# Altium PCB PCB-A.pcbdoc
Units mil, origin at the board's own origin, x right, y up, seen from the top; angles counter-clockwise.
Board outline 5415 x 2695 mil, 4 copper layers (Top Layer, Inner1, Inner2, Bottom Layer); 67 components, 115 nets, 401 pads, 220 vias.
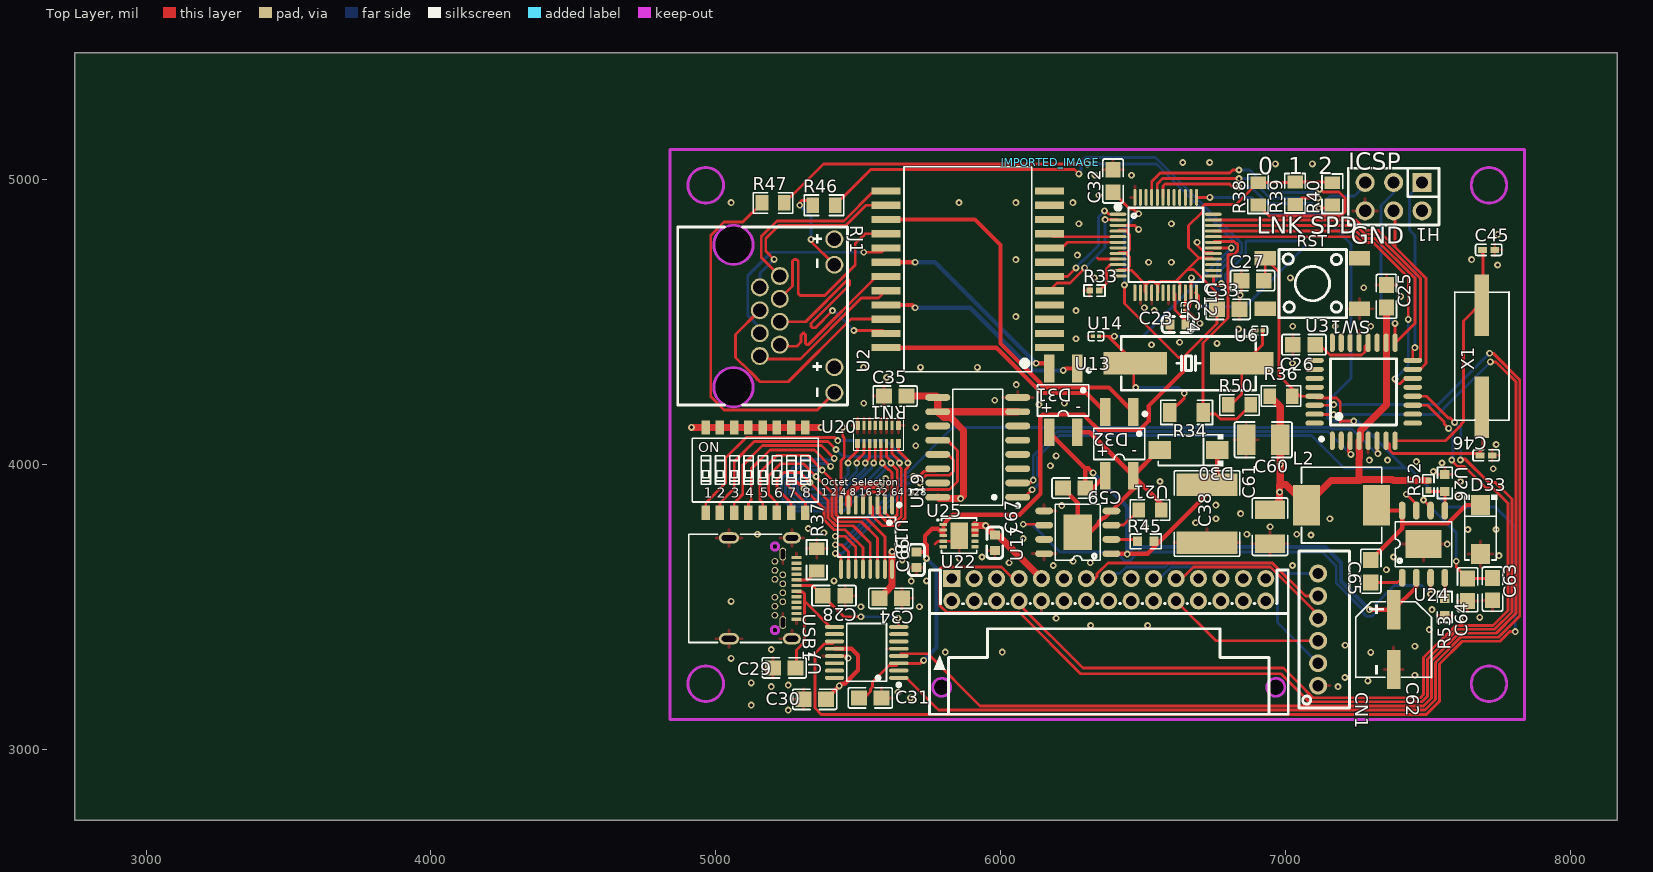
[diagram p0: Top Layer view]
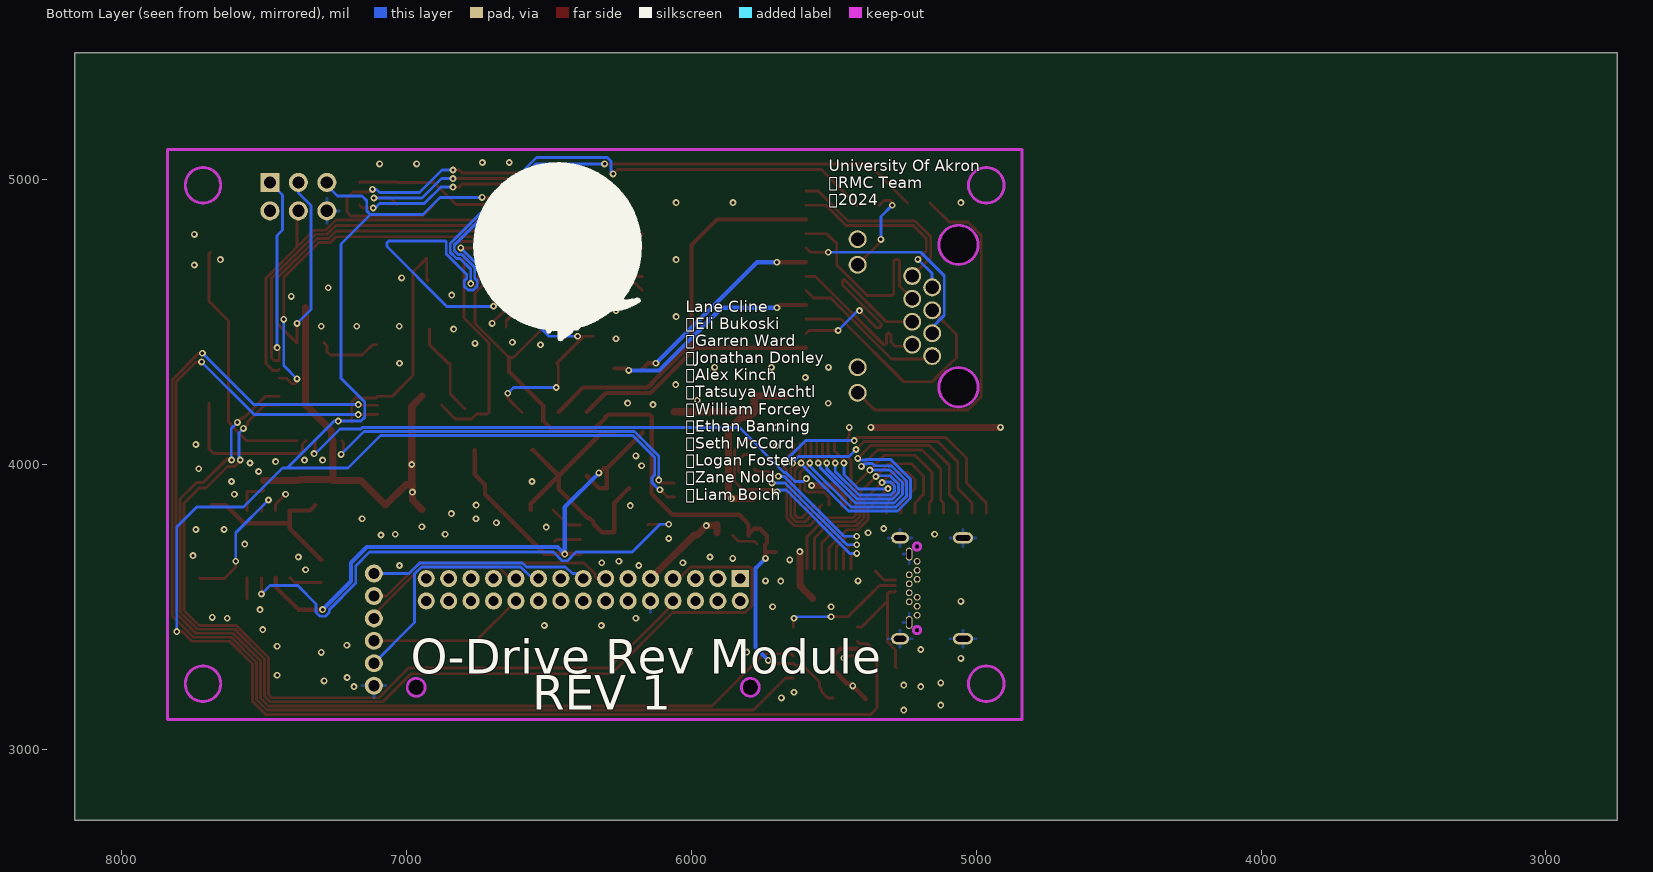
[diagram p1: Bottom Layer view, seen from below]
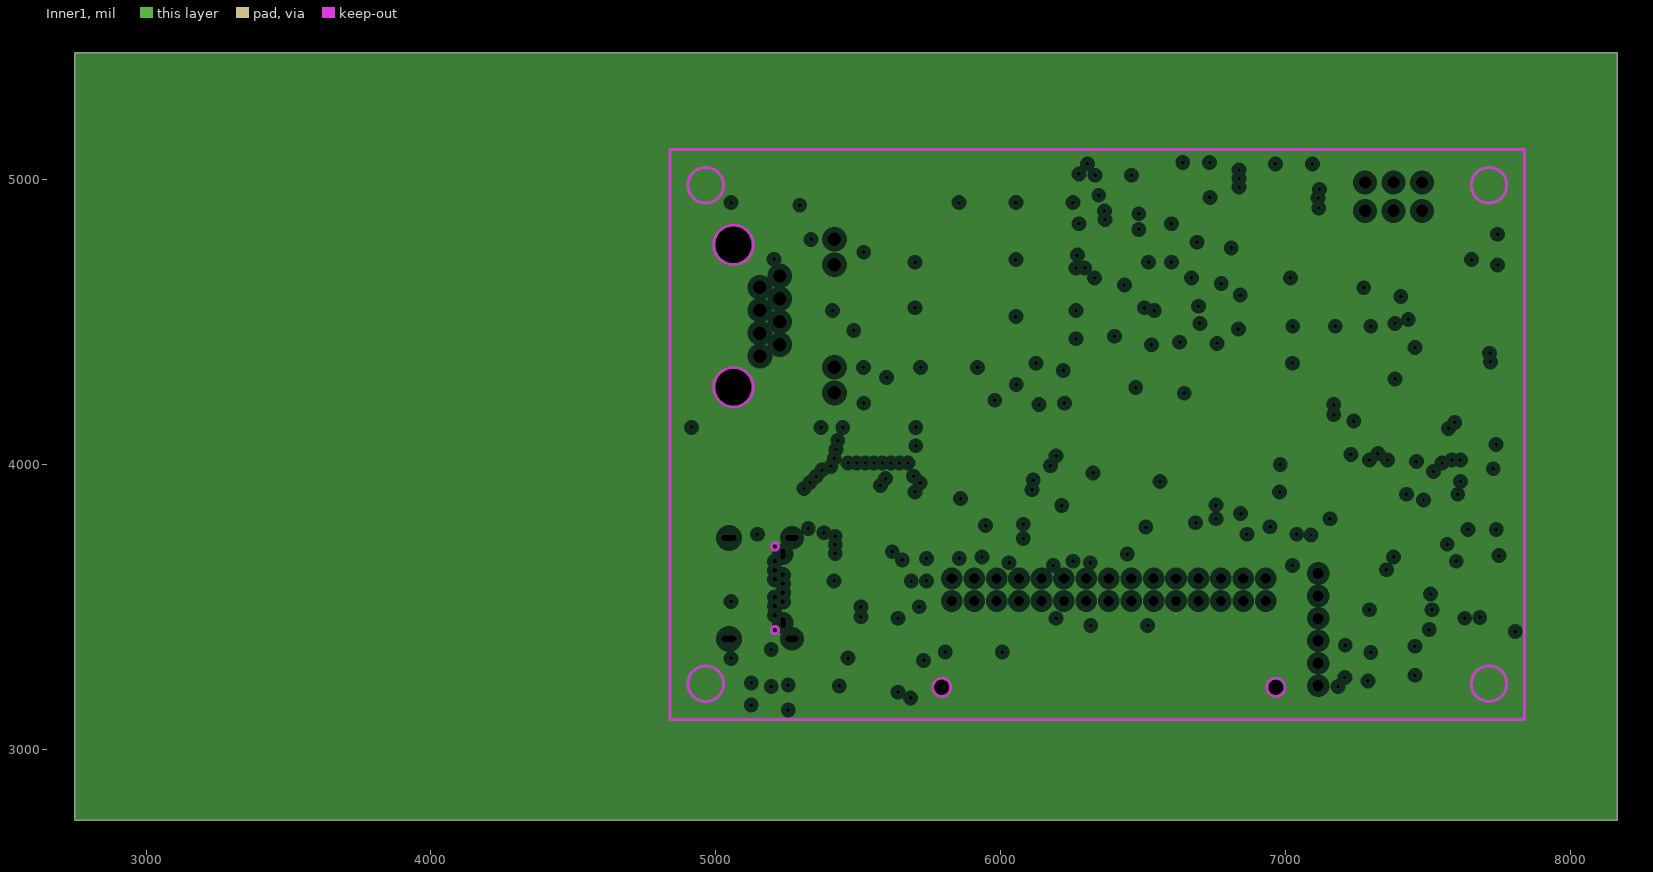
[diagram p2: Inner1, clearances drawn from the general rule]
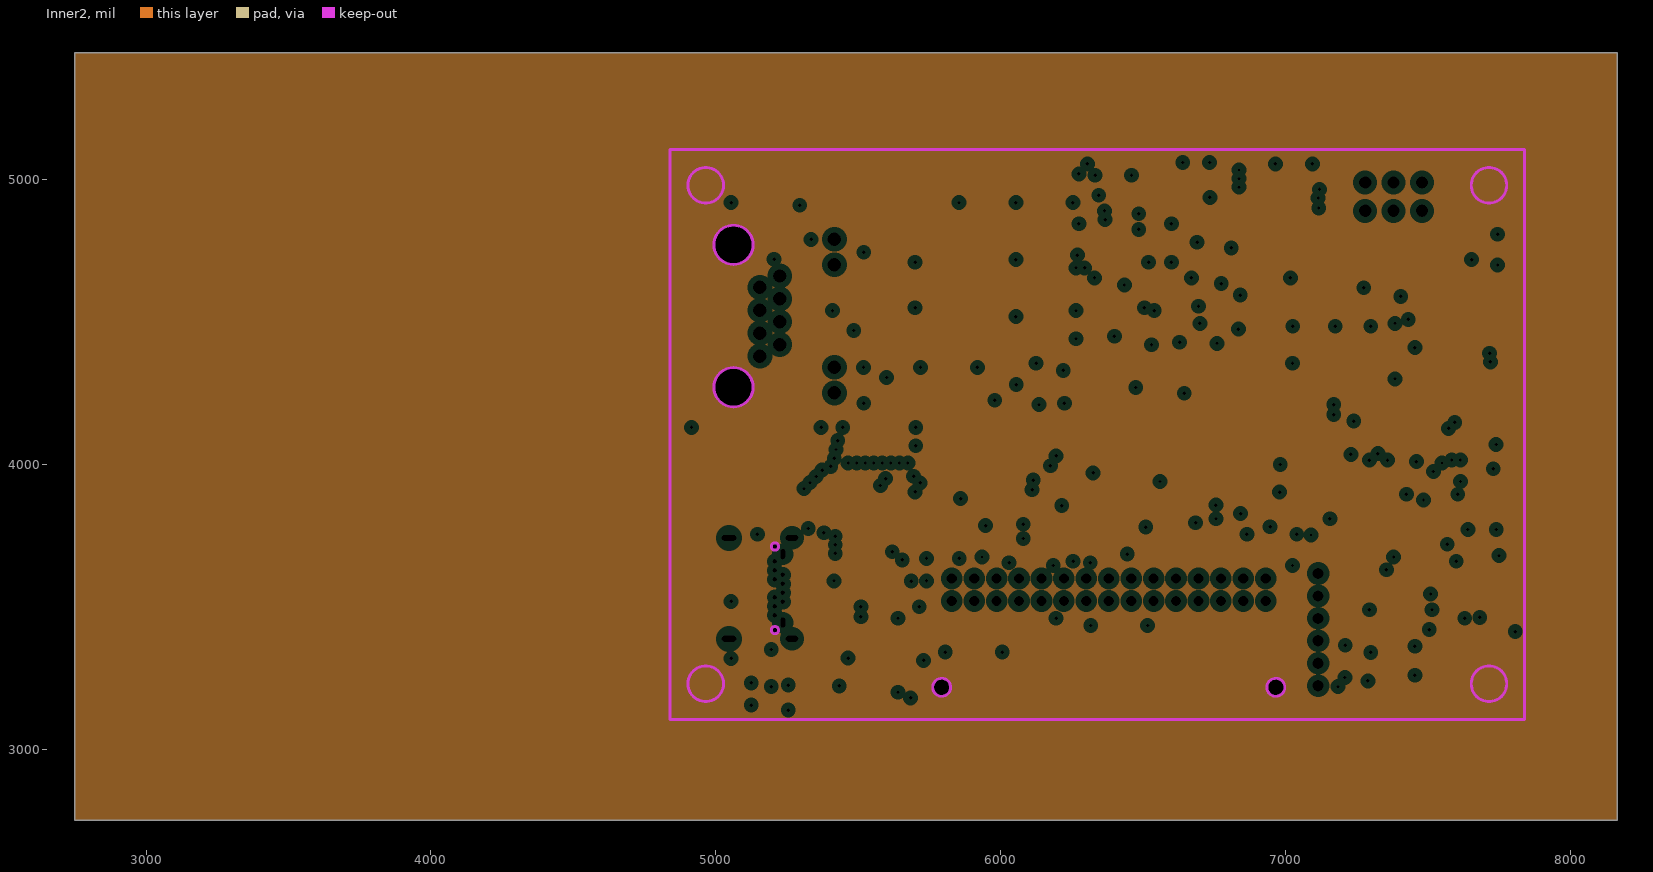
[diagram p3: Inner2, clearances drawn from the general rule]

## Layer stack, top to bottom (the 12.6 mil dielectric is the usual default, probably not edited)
Top Layer: signal copper (thickness not stored)
Dielectric: dielectric 12.6, FR-4, Dk 4.8
Inner1: plane copper (thickness not stored)
Dielectric: dielectric 12.6, FR-4, Dk 4.8
Inner2: plane copper (thickness not stored)
Dielectric: dielectric 12.6, FR-4, Dk 4.8
Bottom Layer: signal copper (thickness not stored)

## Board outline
8165,2750 2750,2750 2750,5445 8165,5445

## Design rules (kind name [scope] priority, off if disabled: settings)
Clearance copperThickness1oz [All] p1: gap=7 ignorepadtopadclearanceinfootprint=FALSE except(4: Track-Track; 6: Track-SMDPad SMDPad-SMDPad Track-THPad SMDPad-THPad THPad-THPad Track-Via SMDPad-Via THPad-Via Via-Via SMDPad-Fill THPad-Fill Via-Fill Fill-Fill Track-Region SMDPad-Region THPad-Region Via-Region Region-Region Track-Poly SMDPad-Poly THPad-Poly Via-Poly Fill-Poly Region-Poly Poly-Poly Track-Text SMDPad-Text THPad-Text Via-Text Fill-Text Region-Text Poly-Text Text-Text; 6.9: Track-Hole SMDPad-Hole THPad-Hole Via-Hole Fill-Hole Region-Hole Poly-Hole Text-Hole Sheet-Hole; 11.8: Track-Fill Fill-Region Track-Sheet SMDPad-Sheet THPad-Sheet Via-Sheet Fill-Sheet Region-Sheet Poly-Sheet Text-Sheet)
Clearance copperThickness2oz [All] p1: gap=7 ignorepadtopadclearanceinfootprint=FALSE except(6: Track-SMDPad SMDPad-SMDPad Track-THPad SMDPad-THPad THPad-THPad Track-Via SMDPad-Via THPad-Via Via-Via SMDPad-Fill THPad-Fill Via-Fill Fill-Fill Track-Region SMDPad-Region THPad-Region Via-Region Region-Region Track-Poly SMDPad-Poly THPad-Poly Via-Poly Fill-Poly Region-Poly Poly-Poly Track-Text SMDPad-Text THPad-Text Via-Text Fill-Text Region-Text Poly-Text Text-Text; 6.9: Track-Hole SMDPad-Hole THPad-Hole Via-Hole Fill-Hole Region-Hole Poly-Hole Text-Hole Sheet-Hole; 8: Track-Track; 11.8: Track-Fill Fill-Region Track-Sheet SMDPad-Sheet THPad-Sheet Via-Sheet Fill-Sheet Region-Sheet Poly-Sheet Text-Sheet)
DiffPairsRouting differentialPair [All] p1: maxuncoupledlength=10 maxlimit=6 mostfreqgap=6 toplayer_minwidth=5 toplayer_prefwidth=10 toplayer_maxwidth=100 bottomlayer_minwidth=5 bottomlayer_prefwidth=10 bottomlayer_maxwidth=100
DiffPairsRouting differentialPair1 [All] p1: maxuncoupledlength=10 maxlimit=6 mostfreqgap=6 toplayer_minwidth=5 toplayer_prefwidth=10 toplayer_maxwidth=100 bottomlayer_minwidth=5 bottomlayer_prefwidth=10 bottomlayer_maxwidth=100
PasteMaskExpansion pasteMaskExpansion [All] p1:
PlaneConnect innerPlane [All] p1: planeconnectstyle=Relief reliefexpansion=20 reliefentries=4 reliefconductorwidth=10 reliefairgap=10
PolygonConnect copperRegion [All] p1: connectstyle=Relief reliefentries=4 reliefconductorwidth=10 polygonreliefangle="90 Angle" airgapwidth=10
RoutingVias viaSize [All] p1: viastyle="Through Hole" holewidth=12 minholewidth=11.8 maxholewidth=248 width=24 minwidth=19.7 maxwidth=393.7
SolderMaskExpansion solderMaskExpansion [All] p1: useseparateexpansions=TRUE expansion=2 expansionbottom=2
Width copperThickness1oz [All] p1: maxlimit=100 minlimit=5 preferedwidth=10
Width copperThickness2oz [All] p1: maxlimit=100 minlimit=8 preferedwidth=10
Width powa [All] p1: maxlimit=50 minlimit=10 preferedwidth=25
Width 3v [All] p1: maxlimit=100 minlimit=10 preferedwidth=15

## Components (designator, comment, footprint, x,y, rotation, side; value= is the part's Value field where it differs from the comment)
C23 "CL10A475KQ8NNNC" C0603 6622.81,4490.85 r0 top
C24 "CL02A103KQ2NNNC" C01005 6645,4550 r270 top
C25 "0805B104K500NT" C0805 7355,4590 r90 top
C26 "0805B104K500NT" C0805 7065.69,4420.24 r0 top
C27 "0805B104K500NT" C0805 6885,4645 r0 top
C28 "CL21C470JBANNNC" C0805 5415.4,3539.06 r180 top
C29 "CL21C470JBANNNC" C0805 5240.7,3285.81 r0 top
C30 "0805B104K500NT" C0805 5347.65,3175.41 r0 top
C31 "0805B104K500NT" C0805 5543,3180.41 r0 top
C32 "0805B104K500NT" C0805 6395,4995 r90 top
C33 "0805B104K500NT" C0805 6799.25,4544.63 r0 top
C34 "0805B104K500NT" C0805 5615,3530 r180 top
C35 "0805B104K500NT" C0805 5630,4240 r0 top
C38 "FS55X106K101EHG" C2220 6724.99,3827.21 r90 top
C45 "CC0402JRNPO9BN120" C0402 7713.97,4753.41 r0 top
C46 "CC0402JRNPO9BN120" C0402 7705,4031.99 r180 top
C59 "0805B104K500NT" C0805 6258.25,3916.73 r180 top
C60 "CS3225X7R476K160NRL" C1210 6922.35,4086.37 r0 top
C61 "CS3225X7R476K160NRL" C1210 6946.27,3781.37 r90 top
C62 "EEEFK1J100P" CAP-SMD_BD6.3-L6.6-W6.6-FD 7380,3385 r270 top
C63 "0805F403M500NT" C0805 7727.35,3562.13 r90 top
C64 "0805F403M500NT" C0805 7640,3560 r90 top
C65 "0805B104K500NT" C0805 7300,3625 r270 top
C66 "CL10A225KO8NNNC" C0603 5705,3665 r90 top
C67 "CL10A225KO8NNNC" C0603 5980,3725 r90 top
CN1 "B6B-PH-K-S(LF)(SN)_C131342" CONN-TH_B6B-PH-K-S 7115,3420 r270 top
D30 "SMAJ58A" SMA_L4.4-W2.8-LS5.4-RD 6660,4050 r180 top
D31 "MB110S_C382811" MBS_L4.7-W4.0-P2.50-LS7.0-BL 6220,4225 r180 top
D32 "MB110S_C382811" MBS_L4.7-W4.0-P2.50-LS7.0-BL 6416.86,4072.27 r180 top
D33 "SS36_C727061" SMA_L4.4-W2.6-LS5.0-RD 7685,3771.37 r270 top
H1 "10897060" HDR-TH_6P-P2.54-V-M-R2-C3-S2.54 7380,4940 r180 top
IMPORTED_IMAGE "IMPORTED_IMAGE" IMPORTED_IMAGE 6175,5060 r0 top
L2 "FXL0630-8R2-M" IND-SMD_L7.0-W6.6_FXL0630 7197.3,3857.13 r0 top
R33 "0402WGF1242TCE" R0402 6330,4610 r0 top
R34 "1206W4F1004T5E" R1206 6653.04,4182.26 r0 top
R36 "0805W8F1002T5E" R0805 6985,4240 r0 top
R37 "ARG05BTC5001N" R0805 5355,3665 r90 top
R38 "0805W8F0000T5E_C17477" R0805 6904.25,4949.88 r90 top
R39 "0805W8F0000T5E_C17477" R0805 7034.25,4951.98 r90 top
R40 "0805W8F0000T5E_C17477" R0805 7165,4950 r90 top
R45 "0603WAF2492T5E" R0603 6510,3730 r0 top
R46 "ARG05DTC2500N" R0805 5380,4910 r0 top
R47 "ARG05DTC2500N" R0805 5201.69,4918 r0 top
R50 "RC0805JR-070RL" R0805 6838.76,4208.94 r0 top
R52 "RC0402FR-07100KL" R0402 7502.16,3926.37 r90 top
R53 "0603WAF4992T5E" R0603 7559.36,3499.4 r90 top
RJ1 "HC-RJ45-5JA-1-5" RJ45-TH_HC-RJ45-5JA-1-5 5285.86,4520.98 r270 top
RN1 "YC248-JR-0710KL" RES-ARRAY-SMD_1606-16P-L4.0-W1.6-BL 5570,4105 r180 top
SW1 "PTS645SK50SMTR92LFS" KEY-SMD_4P-L6.0-W6.0-P4.50-LS9.0 7095,4635 r180 top
U2 "G24102CE-Z" SMD-24_L18.2-W12.2-P1.27_G24102CE-Z 5885,4685 r90 top
U3 "ATMEGA328PB-AU" TQFP-32_L7.0-W7.0-P0.80-LS9.0-BL 7275,4255 r0 top
U6 "GJM0335C1E180GB01D" C0201 6910,4470 r0 top
U7 "FT230XS-R" SSOP-16_L5.0-W4.4-P0.65-LS6.4-BL 5530,3340 r90 top
U12 "W5500" LQFP-48_L7.0-W7.0-P0.50-LS9.0-BL 6580,4770 r270 top
U13 "ECS-250-18-5PX-CKM-TR" HC-49-SMD_L12.0-W4.8 6660,4355 r0 top
U14 "GJM0335C1E180GB01D" C0201 6335,4450 r0 top
U17 "TPS2378DDAR" SO-8_L4.9-W3.9-P1.27-LS6.0-BL-EP 6271.2,3761.73 r90 top
U18 "SN74HC151PWR" TSSOP-16_L5.0-W4.4-P0.65-LS6.4-BL 5530,3745 r180 top
U19 "SN74LS161ANSR" SOIC-16_L10.8-W5.5-P1.27-LS7.8-BL 5920,4060 r90 top
U20 "DV7SA-08F-01" SW-SMD_DV7SA-08F-01 5140,3980 r0 top
U21 "CR0805F863R4G" R0805 6525,3840 r180 top
U22 "S30B-PUDSS-1(LF)(SN)" CONN-TH_S30B-PUDSS-1 6380,3560 r0 top
U24 "LMR16030SDDAR" SO-8_L4.9-W3.9-P1.27-LS6.0-BL-EP 7485,3720 r0 top
U25 "NCP3335AMN330R2G" DFN-10_L3.0-W3.0-P0.50-BL-EP-1 5855,3750 r270 top
U26 "FRC0603F1782TS" R0603 7560,3935 r270 top
USB1 "HC-TYPE-C-24P-DS10.0-CH2.75S-5A-04" USB-TYPE-C-SMD_HC-TYPE-C-24P-DS10.0-CH2.75S-5A-04 5165,3565 r270 top
X1 "X49SM16MSD2SC" HC-49S_L11.4-W4.8 7690,4380 r90 top

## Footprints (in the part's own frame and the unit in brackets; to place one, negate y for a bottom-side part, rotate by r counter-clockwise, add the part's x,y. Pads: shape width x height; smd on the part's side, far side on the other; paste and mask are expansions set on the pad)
C0201 [mil]
  rect 14.51x12.76 smd: 1(-10.8,0) 2(10.8,0)
  silkscreen extent -27,-15 27,15
C0402 [mm]
  rect 0.79x0.54 smd: 1(-0.545,0) 2(0.545,0)
  silkscreen extent -1.17,-0.5 1.17,0.5
C0603 [mm]
  rect 0.8x0.9 smd: 1(-0.7,0) 2(0.7,0)
  silkscreen extent -1.41,-0.71 1.39,0.72
C0805 [mm]
  rect 1.41x1.35 smd: 1(-1,0) 2(1,0)
  silkscreen extent -1.96,-0.9 1.96,0.9
C01005 [mm]
  rect 0.21x0.22 smd: 1(-0.195,0) 2(0.195,0)
  silkscreen extent -0.46,-0.27 0.46,0.27
C1210 [mm]
  rect 1.635x2.7 smd: 1(-1.517,0) 2(1.517,0)
  silkscreen extent -2.56,-1.58 2.56,1.58
C2220 [mm]
  rect 2.01x5.4 smd: 1(-2.58,0) 2(2.58,0)
  silkscreen extent -3.81,-2.93 3.81,2.93
CAP-SMD_BD6.3-L6.6-W6.6-FD [mm]
  rect 3.5x1.2 smd: 1(-2.67,0) 2(2.67,0)
  silkscreen extent -3.38,-3.38 3.38,3.38
CONN-TH_B6B-PH-K-S [mm]
  round 1.6 hole 1: 1(5,0) 2(3,0) 3(1,0) 4(-1,0) 5(-3,0) 6(-5,0)
  silkscreen extent -7,-1.7 7,2.8
CONN-TH_S30B-PUDSS-1 [mil]
  rect 60x60 hole 36: 1(-551.18,39.37)
  round 60 hole 36: 2(-551.18,-39.37) 3(-472.44,39.37) 4(-472.44,-39.37) 5(-393.7,39.37) 6(-393.7,-39.37) 7(-314.96,39.37) 8(-314.96,-39.37) 9(-236.22,39.37) 10(-236.22,-39.37) 11(-157.48,39.37) 12(-157.48,-39.37) 13(-78.74,39.37) 14(-78.74,-39.37) 15(0,39.37) 16(0,-39.37) 17(78.74,39.37) 18(78.74,-39.37) 19(157.48,39.37) 20(157.48,-39.37) 21(236.22,39.37) 22(236.22,-39.37) 23(314.96,39.37) 24(314.96,-39.37) 25(393.7,39.37) 26(393.7,-39.37) 27(472.44,39.37) 28(472.44,-39.37) 29(551.18,39.37) 30(551.18,-39.37)
  Multi-Layer board cut-out: -555.12,-342.52 -558.24,-328.85 -566.98,-317.89 -579.61,-311.81 -593.62,-311.81 -606.25,-317.89 -614.99,-328.85 -618.11,-342.52 -618.11,-342.52 -614.99,-356.19 -606.25,-367.14 -593.62,-373.23 -579.6,-373.23 -566.98,-367.14 -558.24,-356.18 -555.12,-342.52
  Multi-Layer board cut-out: 618.11,-342.52 613.79,-326.9 602.27,-315.5 586.61,-311.33 570.95,-315.5 559.44,-326.9 555.12,-342.52 555.12,-342.52 559.44,-358.14 570.96,-369.54 586.61,-373.71 602.27,-369.54 613.79,-358.14 618.11,-342.52
  Multi-Layer keep-out circle w10: c-586.61,-342.52 r31.5
  Multi-Layer keep-out circle w10: c586.61,-342.52 r31.5
  silkscreen extent -630,-437 630,69
DFN-10_L3.0-W3.0-P0.50-BL-EP-1 [mm]
  rect 0.29x0.65 smd: 1(-1,-1.411) 2(-0.5,-1.411) 3(0,-1.411) 4(0.5,-1.411) 5(1,-1.411) 6(1,1.411) 7(0.5,1.411) 8(0,1.411) 9(-0.5,1.411) 10(-1,1.411)
  rect 2.35x1.58 smd: 11(0,0)
  silkscreen extent -1.58,-1.98 1.58,1.58
HC-49-SMD_L12.0-W4.8 [mm]
  rect 5.7x2 smd: 1(-4.75,0) 2(4.75,0)
  silkscreen extent -6,-2.4 6,2.4
HC-49S_L11.4-W4.8 [mm]
  rect 5.5x1.3 smd: 1(-4.553,0) 2(4.553,0)
  silkscreen extent -5.71,-2.41 5.71,2.41
HDR-TH_6P-P2.54-V-M-R2-C3-S2.54 [mm]
  rect 1.7x1.7 hole 1.1: 1(-2.54,-1.27)
  round 1.7 hole 1.1: 2(-2.54,1.27) 3(0,-1.27) 4(0,1.27) 5(2.54,-1.27) 6(2.54,1.27)
  silkscreen extent -4.04,-2.54 4.04,2.54
IMPORTED_IMAGE [mil]
IND-SMD_L7.0-W6.6_FXL0630 [mm]
  rect 2.424x3.62 smd: 1(3.128,0) 2(-3.128,0)
  silkscreen extent -3.58,-3.38 3.58,3.38
KEY-SMD_4P-L6.0-W6.0-P4.50-LS9.0 [mm]
  rect 1.9x1.3 smd: 1(-4.2,2.25) 2(4.2,2.25) 3(-4.2,-2.25) 4(4.2,-2.25)
  silkscreen extent -3.05,-3.05 2.98,3.05
LQFP-48_L7.0-W7.0-P0.50-LS9.0-BL [mm]
  oval 0.27x1.5 smd: 1(-2.75,-4.25) 2(-2.25,-4.25) 3(-1.75,-4.25) 4(-1.25,-4.25) 5(-0.75,-4.25) 6(-0.25,-4.25) 7(0.25,-4.25) 8(0.75,-4.25) 9(1.25,-4.25) 10(1.75,-4.25) 11(2.25,-4.25) 12(2.75,-4.25) 25(2.75,4.25) 26(2.25,4.25) 27(1.75,4.25) 28(1.25,4.25) 29(0.75,4.25) 30(0.25,4.25) 31(-0.25,4.25) 32(-0.75,4.25) 33(-1.25,4.25) 34(-1.75,4.25) 35(-2.25,4.25) 36(-2.75,4.25)
  oval 1.5x0.27 smd: 13(4.25,-2.75) 14(4.25,-2.25) 15(4.25,-1.75) 16(4.25,-1.25) 17(4.25,-0.75) 18(4.25,-0.25) 19(4.25,0.25) 20(4.25,0.75) 21(4.25,1.25) 22(4.25,1.75) 23(4.25,2.25) 24(4.25,2.75) 37(-4.25,2.75) 38(-4.25,2.25) 39(-4.25,1.75) 40(-4.25,1.25) 41(-4.25,0.75) 42(-4.25,0.25) 43(-4.25,-0.25) 44(-4.25,-0.75) 45(-4.25,-1.25) 46(-4.25,-1.75) 47(-4.25,-2.25) 48(-4.25,-2.75)
  silkscreen extent -3.59,-4.46 3.3,3.34
MBS_L4.7-W4.0-P2.50-LS7.0-BL [mm]
  rect 0.91x2.495 smd: 1(-1.25,-2.848) 2(1.25,-2.848) 3(1.25,2.848) 4(-1.25,2.848)
  silkscreen extent -2.44,-2.82 2.29,1.4
R0402 [mm]
  rect 0.566x0.54 smd: 1(-0.433,0) 2(0.433,0)
  silkscreen extent -0.94,-0.5 0.94,0.5
R0603 [mil]
  rect 31.75x34.02 smd: 1(-29.66,0) 2(29.66,0)
  silkscreen extent -55,-26 55,26
R0805 [mm]
  rect 1.133x1.377 smd: 1(-1,0) 2(1,0)
  silkscreen extent -1.76,-0.92 1.76,0.92
R1206 [mil]
  rect 47.54x66.97 smd: 1(-58.22,0) 2(58.22,0)
  silkscreen extent -91,-42 91,42
RES-ARRAY-SMD_1606-16P-L4.0-W1.6-BL [mm]
  rect 0.45x0.8 smd: 1(-1.825,-0.8) 8(1.825,-0.8) 9(1.825,0.8) 16(-1.825,0.8)
  rect 0.3x0.8 smd: 2(-1.25,-0.8) 3(-0.75,-0.8) 4(-0.25,-0.8) 5(0.25,-0.8) 6(0.75,-0.8) 7(1.25,-0.8) 10(1.25,0.8) 11(0.75,0.8) 12(0.25,0.8) 13(-0.25,0.8) 14(-0.75,0.8) 15(-1.25,0.8)
  silkscreen extent -2.28,-1.39 2.21,1.4
RJ45-TH_HC-RJ45-5JA-1-5 [mm]
  round 1.6 hole 1.2: 1(3.57,-3.325) 2(2.55,-1.545) 3(1.53,-3.325) 4(0.51,-1.545) 5(-0.51,-3.325) 6(-1.53,-1.545) 7(-2.55,-3.325) 8(-3.57,-1.545) 9(-6.85,3.325) 10(-4.57,3.325) 11(4.57,3.325)
  round 1.6 hole 1.2 copper offset 0,0: 12(6.85,3.325)
  Multi-Layer board cut-out: -6.35,-3.925 -7.219,-4.164 -7.853,-4.804 -8.085,-5.675 -7.853,-6.546 -7.219,-7.185 -6.35,-7.425 -6.35,-7.425 -5.481,-7.185 -4.847,-6.546 -4.615,-5.675 -4.847,-4.804 -5.481,-4.164 -6.35,-3.925
  Multi-Layer board cut-out: 6.35,-3.925 5.481,-4.164 4.847,-4.804 4.615,-5.675 4.847,-6.546 5.481,-7.185 6.35,-7.425 6.35,-7.425 7.219,-7.185 7.853,-6.546 8.085,-5.675 7.853,-4.804 7.219,-4.164 6.35,-3.925
  Multi-Layer keep-out circle w0.254: c-6.35,-5.675 r1.75
  Multi-Layer keep-out circle w0.254: c6.35,-5.675 r1.75
  silkscreen extent -7.95,-10.65 7.95,4.5
SMA_L4.4-W2.6-LS5.0-RD [mm]
  rect 1.8x1.7 smd: 1(-2.193,0) 2(2.193,0)
  silkscreen extent -3.11,-1.48 2.73,1.48
SMA_L4.4-W2.8-LS5.4-RD [mil]
  rect 80.57x63.78 smd: 1(-101,0) 2(101,0)
  silkscreen extent -121,-57 106,57
SMD-24_L18.2-W12.2-P1.27_G24102CE-Z [mm]
  rect 0.644x2.6 smd: 1(-6.985,-7.3) 2(-5.715,-7.3) 3(-4.445,-7.3) 4(-3.175,-7.3) 5(-1.905,-7.3) 6(-0.635,-7.3) 7(0.635,-7.3) 8(1.905,-7.3) 9(3.175,-7.3) 10(4.445,-7.3) 11(5.715,-7.3) 12(6.985,-7.3) 13(6.985,7.3) 14(5.715,7.3) 15(4.445,7.3) 16(3.175,7.3) 17(1.905,7.3) 18(0.635,7.3) 19(-0.635,7.3) 20(-1.905,7.3) 21(-3.175,7.3) 22(-4.445,7.3) 23(-5.715,7.3) 24(-6.985,7.3)
  silkscreen extent -9.14,-5.7 9.14,5.7
SO-8_L4.9-W3.9-P1.27-LS6.0-BL-EP [mm]
  oval 0.6x1.6 smd: 1(-1.905,-3) 2(-0.635,-3) 3(0.635,-3) 4(1.905,-3) 5(1.905,3) 6(0.635,3) 7(-0.635,3) 8(-1.905,3)
  rect 3.2x2.5 smd: 9(0,0)
  silkscreen extent -2.5,-2 2.5,2
SOIC-16_L10.8-W5.5-P1.27-LS7.8-BL [mil]
  oval 23.7x87.83 smd: 1(-175,-140.37) 2(-125,-140.37) 3(-75,-140.37) 4(-25,-140.37) 5(25,-140.37) 6(75,-140.37) 7(125,-140.37) 8(175,-140.37) 9(175,140.37) 10(125,140.37) 11(75,140.37) 12(25,140.37) 13(-25,140.37) 14(-75,140.37) 15(-125,140.37) 16(-175,140.37)
  silkscreen extent -211,-146 204,87
SSOP-16_L5.0-W4.4-P0.65-LS6.4-BL [mil]
  oval 13.5x68.17 smd: 1(-89.57,-112.82) 2(-63.98,-112.82) 3(-38.39,-112.82) 4(-12.79,-112.82) 5(12.8,-112.82) 6(38.39,-112.82) 7(63.98,-112.82) 8(89.57,-112.82) 9(89.57,112.82) 10(63.98,112.82) 11(38.39,112.82) 12(12.8,112.82) 13(-12.79,112.82) 14(-38.39,112.82) 15(-63.98,112.82) 16(-89.57,112.82)
  silkscreen extent -120,-119 101,70
SW-SMD_DV7SA-08F-01 [mm]
  rect 0.76x1.27 smd: 1(-4.445,-3.81) 2(-3.175,-3.81) 3(-1.905,-3.81) 4(-0.635,-3.81) 5(0.635,-3.81) 6(1.905,-3.81) 7(3.175,-3.81) 8(4.445,-3.81) 9(4.445,3.81) 10(3.175,3.81) 11(1.905,3.81) 12(0.635,3.81) 13(-0.635,3.81) 14(-1.905,3.81) 15(-3.175,3.81) 16(-4.445,3.81)
  silkscreen extent -5.64,-2.85 5.61,2.85
TQFP-32_L7.0-W7.0-P0.80-LS9.0-BL [mm]
  oval 0.45x1.65 smd: 1(-2.8,-4.369) 2(-2,-4.369) 3(-1.2,-4.369) 4(-0.4,-4.369) 5(0.4,-4.369) 6(1.2,-4.369) 7(2,-4.369) 8(2.8,-4.369) 17(2.8,4.369) 18(2,4.369) 19(1.2,4.369) 20(0.4,4.369) 21(-0.4,4.369) 22(-1.2,4.369) 23(-2,4.369) 24(-2.8,4.369)
  oval 1.65x0.45 smd: 9(4.381,-2.8) 10(4.381,-2) 11(4.381,-1.2) 12(4.381,-0.4) 13(4.381,0.4) 14(4.381,1.2) 15(4.381,2) 16(4.381,2.8) 25(-4.381,2.8) 26(-4.381,2) 27(-4.381,1.2) 28(-4.381,0.4) 29(-4.381,-0.4) 30(-4.381,-1.2) 31(-4.381,-2) 32(-4.381,-2.8)
  silkscreen extent -3.91,-4.36 2.94,2.95
TSSOP-16_L5.0-W4.4-P0.65-LS6.4-BL [mil]
  oval 13.5x68.17 smd: 1(-89.57,-112.82) 2(-63.98,-112.82) 3(-38.39,-112.82) 4(-12.79,-112.82) 5(12.8,-112.82) 6(38.39,-112.82) 7(63.98,-112.82) 8(89.57,-112.82) 9(89.57,112.82) 10(63.98,112.82) 11(38.39,112.82) 12(12.8,112.82) 13(-12.79,112.82) 14(-38.39,112.82) 15(-63.98,112.82) 16(-89.57,112.82)
  silkscreen extent -120,-119 101,70
USB-TYPE-C-SMD_HC-TYPE-C-24P-DS10.0-CH2.75S-5A-04 [mm]
  oval 1x1.6 hole 0.5 slot 1.1 at 90 deg: 25(4.5,2.605) 28(-4.5,2.605)
  oval 1x1.8 hole 0.5 slot 1.3 at 90 deg: 26(4.5,-3.005) 27(-4.5,-3.005)
  rect 0.3x0.9 smd: A1(-2.75,3.005) A2(-2.25,3.005) A3(-1.75,3.005) A4(-1.25,3.005) A5(-0.75,3.005) A6(-0.25,3.005) A7(0.25,3.005) A8(0.75,3.005) A9(1.25,3.005) A10(1.75,3.005) A11(2.25,3.005) A12(2.75,3.005)
  oval 1.15x0.6 hole 0.4 slot 0.9 at 0 deg: B1(3.05,1.795)
  round 0.6 hole 0.4: B2(2.4,1.095) B3(1.6,1.095) B4(1.2,1.795) B5(0.8,1.095) B6(0.4,1.795) B7(-0.4,1.795) B9(-1.2,1.795) B10(-1.6,1.095) B11(-2.4,1.095)
  round 0.6 hole 0.4 copper offset 0,0: B8(-0.8,1.095)
  oval 1.15x0.6 hole 0.4 slot 0.9 at 0 deg copper offset 0,0: B12(-3.05,1.795)
  Multi-Layer board cut-out: -3.725,1.42 -3.866,1.388 -3.979,1.298 -4.042,1.167 -4.042,1.023 -3.979,0.892 -3.866,0.802 -3.725,0.77 -3.725,0.77 -3.584,0.802 -3.471,0.892 -3.408,1.023 -3.408,1.167 -3.471,1.298 -3.584,1.388 -3.725,1.42
  Multi-Layer board cut-out: 3.725,1.42 3.584,1.388 3.471,1.298 3.408,1.167 3.408,1.023 3.471,0.892 3.584,0.802 3.725,0.77 3.725,0.77 3.866,0.802 3.979,0.892 4.042,1.023 4.042,1.167 3.979,1.298 3.866,1.388 3.725,1.42
  Multi-Layer keep-out circle w0.254: c-3.725,1.095 r0.325
  Multi-Layer keep-out circle w0.254: c3.725,1.095 r0.325
  silkscreen extent -4.83,-6.6 4.83,1.71

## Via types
v1: diameter 24, hole 12, Top Layer to Bottom Layer, 151 vias
v2: diameter 24.02, hole 12.01, Top Layer to Bottom Layer, 69 vias

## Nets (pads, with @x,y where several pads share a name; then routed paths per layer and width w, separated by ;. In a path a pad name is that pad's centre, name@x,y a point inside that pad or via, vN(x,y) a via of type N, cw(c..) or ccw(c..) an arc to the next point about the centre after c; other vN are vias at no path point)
$6N1128: D32.2 U2.24 | length 863.5
  Top Layer w15: U2.24 5984.9,4410 6143.9,4251 6301.02,4251 D32.2
$6N1130: D32.1 U2.15 | length 1352.3
  Top Layer w15: U2.15 5910,4860 6000,4770 6000,4425 6139.37,4285.63 6139.37,4282.4 6147.27,4274.5 6150.5,4274.5 6155,4270 6380.46,4270 D32.1
$6N9056: D31.1 U2.21 | length 770.2
  Top Layer w15: U2.21 5690,4560 v1(5700,4550) ; v1(6220,4330) 6227.11,4337.11 D31.1
  Bottom Layer w15: v1(5700,4550) 5893.94,4550 6114.44,4329.5 6135.56,4329.5 6136.06,4330 v1(6220,4330)
$6N9064: D31.2 U2.18 | length 727.6
  Top Layer w15: U2.18 v1(5700,4710) ; v1(6125,4355) 6152.89,4355 D31.2
  Bottom Layer w15: v1(5700,4710) 5770,4710 v1(6125,4355)
$6N10859: U17.3 U21.2 | length 118.4
  Top Layer w10: U17.3 6432.36,3786.73 U21.2
$6N10879: R45.1 U17.2 | length 93.8
  Top Layer w10: U17.2 6473.61,3736.73 R45.1
$6N20463: R47.1 RJ1.12 | length 1271.7
  Top Layer w10: R47.1 5095.2,4850.87 5029.34,4850.87 4982.55,4804.08 4982.55,4237.9 5029.34,4191.11 5356.57,4191.11 RJ1.12
$6N20475: R46.1 RJ1.10 | length 325.2
  Top Layer w10: v2(5295,4910) 5295,4920 5302.07,4927.07 5323.56,4927.07 R46.1 ; v2(5335,4790) 5335,4782.67 RJ1.10
  Bottom Layer w10: v2(5295,4910) 5335,4870 v2(5335,4790)
$6N36570: R53.2 U24.4 | length 73.1
  Top Layer w10: R53.2 7560,3529.7 U24.4
$6N36571: C63.2 C64.2 U24.6 | length 476
  Top Layer w10: v1(7485,3875) 7508.87,3851.13 U24.6@7508.87,3836.98 ; v1(7600,3660) 7600,3639.37 C64.2 7725.22,3599.37 C63.2
  Bottom Layer w10: v1(7485,3875) 7600,3760 v1(7600,3660)
$6N36572: C65.1 D33.1 L2.1 U24.8 | length 620.6
  Top Layer w15: C65.1 7408.51,3772.88 7408.51,3774.81 7410,3776.3 7410,3798.29 ; L2.1 7339.47,3838.11 U24.8 7410,3798.29 ; D33.1 7635.06,3857.69 7570.49,3793.11 7415.17,3793.11 7410,3798.29
$6N36573: R52.1 U24.5 U26.2 | length 126.7
  Top Layer w10: R52.1 7506.15,3905.34 U26.2 U24.5
$6N36578: C65.2 U24.1 | length 116.7
  Top Layer w10: C65.2 7393.74,3585.63 U24.1
$8N817: R33.2 U12.10 | length 134.4
  Top Layer w10: R33.2 6372.17,4635.13 6372.17,4688.17 6385.1,4701.1 U12.10
$8N818: C23.2 U12.20 | length 136.7
  Top Layer w10: U12.20 6612.9,4599.31 6612.9,4542.1 6650.37,4504.63 C23.2@6650.37,4482.93
$8N822: C24.1 U12.22 | length 46.6
  Top Layer w10: C24.1 6648.9,4561.58 U12.22
$8N824: R34.1 U12.30 U13.1 U14.2 | length 1146.5
  Top Layer w10: U14.2 6377.99,4450 ; v2(6400,4450) 6377.99,4450 ; v2(6475,4270) 6467.93,4277.07 6467.93,4349.94 U13.1 6377.99,4450 ; R34.1 6645,4232.44 v2(6645,4250) ; U12.30 6809.84,4760.16 v2(6810,4760)
  Bottom Layer w10: v2(6400,4450) 6500,4450 v2(6810,4760) ; v2(6475,4270) 6625,4270 v2(6645,4250)
$8N825: R34.2 R50.2 U12.31 | length 939.5
  Top Layer w10: U12.31 6750.47,4782.99 6819.52,4782.99 6827.52,4775 6830,4775 6832.99,4772.01 6832.99,4750.48 6819.52,4737.01 6799.94,4737.01 6798.62,4735.69 6798.62,4513.51 6711.26,4426.15 R34.2 6716.26,4177.26 6754.66,4177.26 6771.92,4160 6829.18,4160 R50.2
$8N831: R50.1 U6.2 U13.2 | length 335.5
  Top Layer w10: R50.1@6795.34,4195 6847.01,4246.67 U13.2 6854.2,4355 6919.2,4420 U6.2@6919.2,4475
$8N1422: R38.1 U12.45 | length 1177.1
  Top Layer w10: U12.45 6530.79,4993.16 6560.92,5023.29 6805,5023.29 6815.32,5033.61 v2(6837.33,5033.61) ; R38.1 6942.16,4872.6 7196.44,4872.6 7210,4886.15 7210,4935 7188.91,4956.09 7133.34,4956.09 7124.12,4965.32 v2(7119.9,4965.32)
  Bottom Layer w10: v2(6837.33,5033.61) 6876.39,5033.61 6955,4955 7095,4955 7105.32,4965.32 v2(7119.9,4965.32)
$8N1426: R39.1 U12.44 | length 738.2
  Top Layer w10: U12.44 6550.47,4985 6569.08,5003.61 v2(6837.33,5003.61) ; R39.1 7056.95,4935.32 v2(7114.9,4935.32)
  Bottom Layer w10: v2(6837.33,5003.61) 6877.81,5003.61 6946.1,4935.32 v2(7114.9,4935.32)
$8N1431: R40.1 U12.43 | length 676.2
  Top Layer w10: U12.43 6570.16,4976.85 6577.23,4983.92 6805,4983.92 6815.32,4973.61 v2(6837.33,4973.61) ; v2(7117.33,4900.32) 7154.69,4900.32 R40.1
  Bottom Layer w10: v2(6837.33,4973.61) 6879.97,4973.61 6937.94,4915.63 7095,4915.63 7110.32,4900.32 v2(7117.33,4900.32)
$9N2639: C26.2 U3.20 | length 230.7
  Top Layer w10: C26.2 7119.84,4420.24 7156.54,4383.54 7267.47,4383.54 7279.09,4395.16 7279.09,4415.35 U3.20
$9N2658: R37.1 USB1.A5 | length 84.6
  Top Layer w10: USB1.A5 5323.9,3594.53 R37.1
+5V: C25.1 C30.2 C34.2 C35.2 C60.2 C61.2 C67.2 H1.2 L2.2 R36.1 R52.2 RJ1.9 RJ1.11 U3.4 U3.18 U7.12 U18.7 U18.16 U19.7 U19.9 U19.10 U19.16 U20.9 U20.10 U20.11 U20.12 U20.13 U20.14 U20.15 U20.16 U22.9 U25.8 U25.9 U25.10 | length 3989.5
  Top Layer w15: C30.2 5441.78,3230.18 5452.9,3230.18 5500,3277.28 5500,3330 5477.2,3352.8 U7.12
  Top Layer w25: v1(4915,4130) U20.16 U20.15 U20.14 U20.13 U20.12 U20.11 U20.10 U20.9 v1(5370,4130) ; U18.7 5466.36,3858.16 5466.36,3895.62 5495.13,3924.39 5532.59,3924.39 5534.09,3925.89 v1@5577.52,3925.89 ; C34.2 5608.11,3562.48 5608.11,3564.24 5619.57,3575.69 U18.16 v1(5619.57,3693.64) ; C35.2 5774.63,4240 U19.9 U19.10 ; U19.16 5784.63,3880 v1(5860,3880) 5870.05,3890.05 5870.05,4119.57 5824.27,4165.35 5799.28,4165.35 U19.10 ; 5910.57,3760 U25.9 U25.10 ; U25.10@5915,3785 v1(5947.56,3785) C67.2 5990.59,3752.56 U22.9 ; U19.7 U19.10 ; R36.1 6982.09,4203.54 C60.2 v1(6982.09,3999.62) 6982.09,3932.09 6980,3930 ; C61.2 6980,3874.84 v1(6980,3902.73) 6980,3930 ; C25.1 7355,4508.14 7354.49,4507.64 7354.49,4287.36 7355,4286.86 7355,4209.56 7263.39,4117.95 7263.39,4087.14 U3.4 7259.25,4048.89 7260.51,4047.64 7260.51,4022.36 7259.25,4021.11 7259.25,3945.76 7261.6,3943.41 ; R52.2 7379.31,3943.41 7375.83,3946.89 7265.07,3946.89 7261.6,3943.41 ; 6980,3930 7001.28,3930 L2.2 7160.43,3943.41 7261.6,3943.41
  other v1: 5434.02,3222.41 5578.23,3925.89
+33V: C31.1 C32.1 C33.1 C66.2 R38.2 R39.2 R40.2 U7.3 U12.4 U12.8 U12.11 U12.15 U12.17 U12.21 U12.28 U25.1 U25.2 U25.3 | length 4931.6
  Top Layer w10: C31.1 5521.63,3180.41 5543.63,3202.42 5543.63,3211.54 5550.07,3217.97 5550.07,3235.68 5608.15,3293.76 5634.97,3293.76 U7.3 5719.62,3301.61 v2(5730,3311.99) ; C32.1 6453.56,4897.07 6464.72,4897.07 6471.79,4890 6475,4890 v2(6485,4880) ; U12.8 6416.07,4743.86 6443.64,4743.86 ; U12.4 6416.07,4822.6 6443.64,4822.6 6443.64,4815.83 6453.19,4806.28 6453.19,4753.41 6443.64,4743.86 ; v2(6435,4630) 6435,4565 6624.68,4375.32 6640.61,4375.32 6759.88,4494.59 C33.1 6759.88,4601.89 6677.79,4683.98 6657.07,4683.98 ; U12.15 6507.72,4606.06 6507.72,4633.64 ; U12.21 6630.83,4604.3 6630.83,4633.64 6621.28,4643.19 6616.28,4643.19 ; 6706.79,4885.01 6660,4838.21 6660,4761.43 6697.26,4724.17 ; 6710,4888.21 6710,4905 6717.07,4912.07 6827.07,4912.07 R38.2 7032.14,4989.25 R39.2 7163.02,4991.35 R40.2 ; U12.28 6743.94,4724.17 6697.26,4724.17 ; 6443.64,4743.86 6443.64,4737.09 6453.19,4727.54 6453.19,4694.35 6443.64,4684.8 6416.06,4684.8 U12.11 6459.94,4681.42 6507.72,4633.64 ; 6507.72,4633.64 6514.49,4633.64 6524.04,4643.19 6537.54,4643.19 6550.47,4630.26 U12.17 6553.86,4606.07 6553.86,4633.64 6563.41,4643.19 6616.28,4643.19 ; 6616.28,4643.19 6657.07,4683.98 ; 6657.07,4683.98 6697.26,4724.17
  Top Layer w15: C66.2 5741.99,3692.56 ; v1(5740,3670) 5741.99,3671.99 5741.99,3692.56 ; U25.3 U25.3@5799.43,3755 ; 6640.61,4375.32 6640.61,4325.61 6520,4205 6520,4152.18 6489.59,4121.76 6344.14,4121.76 6300.63,4165.27 6300.63,4167.6 6292.73,4175.5 6147.27,4175.5 6139.37,4167.6 6139.37,3956.71 6140.51,3955.57 6140.51,3897.22 6066.79,3823.5 5832.05,3823.5 5810.4,3801.85 5810.4,3800.34 U25.1 U25.2 U25.3@5799.43,3755 ; 5741.99,3692.56 5741.99,3716.74 5734.59,3724.14 5734.59,3749.59 5759.11,3774.11 5780.32,3774.11 U25.3@5799.43,3755
  Bottom Layer w10: v2(6435,4630) 6435,4830 v2(6485,4880)
  Bottom Layer w15: v2(5730,3311.99) 5775,3356.99 5775,3635 v1(5740,3670)
A0: U3.23
A1: U3.24
A2: U3.25
A3: U3.26
A4: U3.27
A5: U3.28
A6: U3.19
A7: U3.22
AGND: C23.1 C24.2 C25.2 C26.1 C27.1 C28.1 C29.1 C30.1 C31.2 C32.2 C33.2 C34.1 C35.1 C38.1 C45.2 C46.1 C60.1 C61.1 C62.2 C63.1 C64.1 C66.1 C67.1 CN1.1 D33.2 H1.6 R33.1 R37.2 R53.1 RN1.1 RN1.2 RN1.3 RN1.4 RN1.5 RN1.6 RN1.7 RN1.8 SW1.1 U3.5 U3.21 U6.1 U7.5 U7.13 U12.3 U12.9 U12.14 U12.16 U12.19 U12.23 U12.29 U12.48 U14.1 U17.5 U17.8 U18.8 U19.8 U22.10 U24.7 U24.9 U25.4 U25.11 U26.1 USB1.25 USB1.26 USB1.27 USB1.28 USB1.A1 USB1.A12 USB1.B1 USB1.B12 | length 925.3
  Top Layer w10: U7.13 5457.79,3327.21 v1(5465,3320) ; U18.8 5440.43,4012.97 5451.55,4024.08 5451.55,4093.07 5445.82,4098.79 v1(5445.82,4130) ; 5770,3720 5780.31,3730.31 U25.4 5835.31,3730.31 U25.11 ; 6340,4725 6344.21,4720.79 U12.9 ; U12.3 6471.1,4838.9 v1(6485,4825) ; C24.2 6645.23,4542.55 6653.89,4542.55 ; v1(6670.31,4654.69) 6668.58,4652.96 U12.23 6668.58,4565.9 6662.9,4560.22 6662.9,4551.56 6653.89,4542.55 ; v1(6690,4780) 6690,4770.19 6716.35,4743.85 6743.94,4743.85 U12.29 ; v1(6700,4495) 6700,4496.43 6653.89,4542.55 ; v1(7425,3895) 7460,3860 U24.7
  other v1: 5255,3137.53 5125,3155 5684.44,3180.41 5640,3200 5195,3220 7185,3220 5255,3225 5125,3233.03 7290,3240 7209.27,3251.81 7455,3260 5054.1,3319.1 7300,3340 5806.06,3340.91 6006.06,3340.91 5195,3350.21 7455,3361.75 7210,3365 7505,3420 6316.5,3434.47 6516.5,3434.47 6195,3460 7630,3460 7682.48,3462.95 7515,3490 5510,3500 5715,3500 5054.1,3519.1 5686.31,3590.3 5415.4,3591.09 5740.08,3590.9 7355,3630 6185,3645 7025,3645 6030,3655 6315,3655 6255,3660 5655.14,3664.7 5855,3670 5935,3675 7380,3675 7750,3680 7568.47,3720 6080,3740 7089.95,3752.04 5146.55,3755 6865,3755 7040,3755 5380,3760 7641.13,3771.37 7740.16,3771.37 5325,3775 6510,3780 6946.27,3781.37 6685,3795 6756.62,3809.1 7156.62,3809.1 6843.01,3827.21 6214.7,3855.18 6756.17,3857.13 7605,3895 6560,3940 7615,3940 7520,3975 7730,3985 6175,3995 7550,4005 7460,4010 7295,4015 7358.57,4015 6195,4030 5702.21,4065.79 7740,4070 5702.21,4130 6135,4210 5520,4215 6224.15,4215.03 5980,4225 6055,4280 5600,4305 5518.95,4340.64 5718.95,4340.64 5918.95,4340.64 7025,4355 6530,4420 6760,4425 6628.56,4429.16 6265,4441.44 6835,4475 7025.91,4485 7175.37,4485 7300,4485 6054.1,4519.1 6265,4540 6540,4540 6505,4550 7405,4590 6841.67,4594.41 7275,4620 6330,4655 7017.72,4654.81 7745,4700 6520,4710 6600,4710 6054.1,4719.1 7654.1,4719.1 6270,4735 7745,4807.74 6275,4845 6600,4845 5054.1,4919.1 5854.1,4919.1 6054.1,4919.1 6254.1,4919.1 6345,4945 6332.1,5015 6460,5015 6965,5055 7095,5055 6640,5060 6734.09,5060
CAN_H: U22.1
CAN_H2: U22.3
CAN_L: U22.2
CAN_L2: U22.4
CDB: U17.6 U24.3 | length 1835.4
  Top Layer w10: v1(6080,3790) 6149.81,3790 U17.6 ; v1(7510,3545) U24.3
  Bottom Layer w10: v1(6080,3790) 6110,3790 6208,3692 6405.47,3692 6435.47,3662 6454.53,3662 6484.53,3692 7129.95,3692 7178.5,3643.45 7178.5,3583.17 7272,3489.67 7272,3480.47 7285.47,3467 7304.53,3467 7318,3480.47 7318,3510.47 7382.53,3575 7480,3575 v1(7510,3545)
CS0: U18.11 U19.14 | length 622.9
  Top Layer w10: v2(5420,3747.74) 5453.8,3747.74 5491.61,3709.93 U18.11 ; v2(5694.79,3958.15) 5714.27,3958.15 5732.3,3976.18 5770.81,3976.18 U19.14
  Bottom Layer w10: v2(5420,3747.74) 5464.61,3747.74 5675.02,3958.15 v2(5694.79,3958.15)
CS1: U18.10 U19.13 | length 745.3
  Top Layer w10: v2(5420,3717.74) 5441.38,3717.74 5466.02,3693.1 U18.10 ; v2(5717.72,3935.16) 5724.73,3942.17 5724.73,3948.79 5738.1,3962.17 5821.16,3962.17 5834.53,3975.54 5834.53,4015.47 5815,4035 U19.13
  Bottom Layer w10: v2(5420,3717.74) 5454.43,3717.74 5671.85,3935.16 v2(5717.72,3935.16)
CS2: U18.9 U19.12 | length 798.3
  Top Layer w10: v2(5420,3687.74) 5428.95,3687.74 5440.43,3676.26 U18.9 ; v2(5700,3903.31) 5708.85,3912.17 5821.16,3912.17 5848.55,3939.56 5848.55,4049.31 5812.86,4085 U19.12
  Bottom Layer w10: v2(5420,3687.74) 5444.26,3687.74 5666.51,3910 v2@5700,3910
D0: U3.30 U7.1 | length 4103.8
  Top Layer w10: U7.1 5669.57,3250.43 5782.2,3137.8 7490.81,3137.8 7527.4,3174.38 7527.4,3305 7615.4,3393 7748,3393 7823.2,3468.2 7823.2,4296.8 7730,4390 v2(7716.96,4390) ; U3.30 7167.76,4207.76 v2(7170,4210)
  Bottom Layer w10: v2(7170,4210) 7536.96,4210 v2(7716.96,4390)
D1: U3.31 U7.4 | length 4083.6
  Top Layer w10: U7.4 5650.61,3335 5745,3335 5928.15,3151.85 7485.04,3151.85 7513.4,3180.2 7513.4,3310.8 7609.6,3407 7740.19,3407 7809.2,3476.01 7809.2,4290.93 7740.13,4360 v2(7720,4360) ; U3.31 7103.76,4175 v2(7170,4175)
  Bottom Layer w10: v2(7170,4175) 7535,4175 v2(7720,4360)
D2: U3.32
D3: U3.1
D4: U3.2
D5: U3.9
D6: U3.10
D7: U3.11 U22.8 | length 2987.6
  Top Layer w10: U22.8 6065.04,3509 6289.04,3285 6993.28,3285 7072.5,3205.78 7072.5,3205.55 7097.4,3180.65 7474.25,3180.65 7485.4,3191.8 7485.4,3322.4 7598,3435 7728.6,3435 7781.2,3487.6 7781.2,3863.8 7727.93,3917.07 7704.64,3917.07 7629.3,3992.41 7604.92,3992.41 7584.44,4012.89 v1(7584.44,4015.41) ; U3.11 7498.96,4207.76 7557.66,4149.05 7557.66,4141.98 v2(7573.22,4126.42)
  Bottom Layer w10: v2(7573.22,4126.42) 7588.79,4110.86 7588.79,4019.76 v1(7584.44,4015.41)
D8: U3.12 U22.7 | length 3745.4
  Top Layer w10: U22.7 6044.28,3599.37 6003.28,3640.37 5794.26,3640.37 5787.82,3633.93 5787.82,3503.65 5811.84,3479.63 6066.13,3479.63 6280.76,3265 6985,3265 7083.35,3166.65 7480.05,3166.65 7499.4,3186 7499.4,3316.6 7603.8,3421 7734.4,3421 7795.2,3481.8 7795.2,3878.08 7736.21,3937.07 7712.93,3937.07 7630,4020 7619.03,4020 v1(7614.44,4015.41) ; U3.12 7495.75,4239.25 7571.81,4163.19 7578.88,4163.19 v2(7594.44,4147.63)
  Bottom Layer w10: v2(7594.44,4147.63) 7615.86,4126.21 7615.86,4016.83 v1(7614.44,4015.41)
D9: U3.13
DIR: U22.11
DN1: C29.2 U7.9 USB1.A7 | length 448.5
  Top Layer w10: C29.2 5283.31,3289.05 5283.31,3348.42 5312.01,3377.12 5312.01,3519.93 ; USB1.A7 5286.11,3552.36 5305.58,3552.36 5312.01,3545.93 5312.01,3519.93 ; U7.9 5402.37,3429.57 5312.01,3519.93
DP1: C28.2 U7.8 USB1.A6 | length 435.9
  Top Layer w10: USB1.A6 5340.25,3574.84 C28.2 5450.09,3465 v2(5510,3465) ; v2(5640,3460) 5642.82,3457.18 U7.8
  Bottom Layer w10: v2(5510,3465) 5635,3465 v2(5640,3460)
ENCO_A: U22.17
ENCO_B: U22.18
ENCO_Z: U22.20
ETH1A: U2.2
ETH1B: U2.3
ETH2A: U2.5 U12.2 | length 402.6
  Top Layer w10: U2.5 6198.74,4636.34 6243.85,4636.34 6295,4687.48 v2(6295,4690) ; v2(6367.07,4859.53) 6411.73,4859.53 U12.2
  Bottom Layer w10: v2(6295,4690) 6367.07,4762.07 v2(6367.07,4859.53)
ETH2B: U2.6 U12.1 | length 400.5
  Top Layer w10: U2.6 6235,4660 v2(6265,4690) ; v2(6365,4890) 6367.93,4887.07 6372.07,4887.07 6380.87,4878.27 U12.1
  Bottom Layer w10: v2(6265,4690) 6271.99,4696.99 6271.99,4699.53 6285.47,4713.01 6288.01,4713.01 6344.06,4769.06 6344.06,4869.06 v2(6365,4890)
ETH3A: U2.8 U12.6 | length 248.6
  Top Layer w10: U2.8 6215,4760 6235,4780 6412.52,4780 U12.6
ETH3B: U2.9 U12.5 | length 244.6
  Top Layer w10: U2.9 6182.87,4799.53 U12.5
ETH4A: U2.11
ETH4B: U2.12
HALL_A: CN1.4 U22.21 | length 604.9
  Top Layer w10: U22.21 6636.98,3599.37 6677.98,3640.37 6948.16,3640.37 7122.08,3466.45 CN1.4
HALL_B: CN1.3 U22.22 | length 556.8
  Top Layer w10: U22.22 6756.22,3380.63 CN1.3
HALL_C: CN1.2 U22.19 | length 835.3
  Bottom Layer w10: U22.19 6558.24,3599.37 6599.24,3640.37 6948.16,3640.37 6972.18,3616.35 6972.18,3444.71 CN1.2
IP0: RN1.16 U18.4 U20.1 | length 1390.7
  Top Layer w10: U20.1 4965,3865 5035,3935 5035,4021.98 5107.03,4094.02 5418.06,4094.02 v2(5428.54,4083.54) ; U18.4 5550.65,3849.96 5550.65,3819.35 5585.28,3784.72 5638.53,3784.72 5665.34,3811.53 5665.34,3980.37 5675,3990.03 v2(5675,4005) 5675,4014.6 5641.85,4047.75 RN1.16
  Bottom Layer w10: v2(5428.54,4083.54) 5598.98,4083.54 5667.99,4014.52 5667.99,4012.01 v2(5675,4005)
IP1: RN1.15 U18.3 U20.2 | length 1242.3
  Top Layer w10: U20.2 5015,3865 5065,3915 5065,4009.56 5135.44,4080 5394.56,4080 v2(5422.28,4052.28) ; U18.3 5576.24,3849.97 5576.24,3823.15 5600.65,3798.74 5632.72,3798.74 5651.32,3817.34 5651.32,3985.98 5645,3992.31 v2(5645,4005) 5645,4012.58 5619.21,4038.37 RN1.15
  Bottom Layer w10: v2(5422.28,4052.28) 5446.57,4027.99 5624.52,4027.99 5645,4007.52 v2(5645,4005)
IP2: RN1.14 U18.2 U20.3 | length 1655.3
  Top Layer w10: U20.3 5065,3865 5095,3895 5095,3997.13 5163.85,4065.98 5371.15,4065.98 v2(5416.07,4021.07) ; U18.2 5593.98,3831 5612.22,3812.76 5626.92,3812.76 5637.31,3823.15 5637.31,3980.18 5622.01,3995.48 5622.01,3997.99 v2(5615,4005) 5615,4011.19 5599.53,4026.66 RN1.14
  Bottom Layer w10: v2(5416.07,4021.07) 5410.98,4015.99 5389.99,4015.99 5388.97,4017.01 5300.21,4017.01 5230.94,3947.75 5230.94,3882.25 5277.25,3835.95 5448.46,3835.95 5607.99,3995.48 5607.99,4002.99 5610,4005 v2(5615,4005)
IP3: RN1.13 U18.1 U20.4 | length 1389.6
  Top Layer w10: U20.4 5115,3865 5125,3875 5125,3984.71 5190.29,4050 5346.63,4050 v2(5403.64,3992.99) ; RN1.13 5579.84,4010.16 v2(5585,4005) 5592.01,3997.99 5592.01,3995.48 5605.48,3982.01 5607.99,3982.01 5619.57,3970.43 U18.1
  Bottom Layer w10: v2(5403.64,3992.99) 5403.18,3992.99 5394.19,4001.99 5384.19,4001.99 5383.17,4003.01 5364.11,4003.01 5356.59,3995.49 5308.51,3995.49 5307.44,3994.42 5297.46,3994.42 5244.98,3941.93 5244.98,3888.07 5283.07,3849.98 5439.95,3849.95 5585,3995 v2(5585,4005)
IP4: RN1.12 U18.15 U20.5 | length 1525.2
  Top Layer w10: U20.5 5165,3865 5155,3875 5155,3972.28 5214.79,4032.07 5322.93,4032.07 5373.64,3981.36 v2(5373.64,3980) 5422.69,3930.95 5422.69,3823.15 5433.08,3812.76 5527.24,3812.76 5593.98,3746.02 U18.15 ; v2(5555,4005) 5560.16,4010.16 RN1.12
  Bottom Layer w10: v2(5373.64,3980) 5362.37,3980 5361.95,3980.42 5303.26,3980.42 5258.98,3936.13 5258.98,3893.87 5288.87,3863.98 5423.98,3863.98 5548.01,3988.01 5548.01,3998.01 v2(5555,4005)
IP5: RN1.11 U18.14 U20.6 | length 1333.2
  Top Layer w10: U20.6 5215,3865 5185,3895 5185,3959.85 5227.22,4002.07 5307.78,4002.07 v2(5352.43,3957.43) 5408.68,3901.17 5408.68,3817.34 5427.28,3798.74 5511.11,3798.74 5568.39,3741.46 U18.14 ; v2(5525,4005) 5532.01,4012.01 5532.01,4014.52 5540.47,4022.99 RN1.11
  Bottom Layer w10: v2(5352.43,3957.43) 5349.85,3960 5302.66,3960 5272.99,3930.33 5272.99,3899.67 5294.67,3877.99 5417.99,3877.99 5525,3985 v2(5525,4005)
IP6: RN1.10 U18.13 U20.7 | length 1133.7
  Top Layer w10: U20.7 5265,3865 5215,3915 5215,3947.43 5239.64,3972.07 5295.36,3972.07 v2(5331.21,3936.21) 5394.66,3872.76 5394.66,3811.53 5421.47,3784.72 5482.7,3784.72 5542.79,3724.64 U18.13 ; v2(5495,4005) 5495,4012.58 5520.79,4038.37 RN1.10
  Bottom Layer w10: v2(5331.21,3936.21) 5329.43,3937.99 5300.48,3937.99 5287.01,3924.52 5287.01,3905.48 5300.48,3892.01 5412.01,3892.01 5495,3975 v2(5495,4005)
IP7: RN1.9 U18.12 U20.8 | length 899.7
  Top Layer w10: U20.8 5315,3865 5250,3930 5250,3940 5252.07,3942.07 5282.93,3942.07 v2(5310,3915) 5380.65,3844.35 5380.65,3805.73 5415.67,3770.71 5454.29,3770.71 5517.2,3707.8 U18.12 ; v2(5465,4005) 5465,4014.6 5498.15,4047.75 RN1.9
  Bottom Layer w10: v2(5310,3915) 5319.91,3915 5321.69,3913.22 5413.22,3913.22 5465,3965 v2(5465,4005)
LINKLED: R46.2 U12.25 | length 1892.8
  Top Layer w10: R46.2 5544.37,5035 6260,5035 v2(6275,5020) ; U12.25 6747.32,4638.54 6757.93,4627.93 6767.93,4627.93 v2(6775,4635)
  Bottom Layer w10: v2(6275,5020) 6282.01,5027.01 6282.01,5064.52 6295.48,5077.99 6544.34,5077.99 6847.01,4775.33 6847.01,4744.67 6825.33,4722.99 6812.63,4722.99 6775,4685.36 v2(6775,4635)
MISO: H1.1 U3.16 U12.34 | length 1768
  Top Layer w10: U12.34 7248.42,4838.9 7279.33,4807.99 7320,4807.99 7474.37,4653.62 7474.37,4374.37 7465.24,4365.24 U3.16 7447.5,4402.5 v2(7455,4410)
  Bottom Layer w10: v2(7455,4410) 7455,4803.46 7435.55,4822.91 7435.55,4945.55 H1.1
MOSI: H1.4 U3.15 U12.35 | length 1318.6
  Top Layer w10: U12.35 7248.56,4858.58 7285.13,4822.01 7325.81,4822.01 7385,4762.81 ; H1.4 7385,4885 7385,4762.81 ; U3.15 7451.24,4330 7470,4330 7494.05,4354.05 7494.05,4653.76 7385,4762.81
OCTCLK: U3.3 U19.2 | length 1380.6
  Top Layer w10: U19.2 6105,3935 v2(6115,3945) ; U3.3 7222.07,4077.32 7222.07,4042.93 v2(7230,4035)
  Bottom Layer w10: v2(6115,3945) 6115,4029.8 6200.2,4115 7150,4115 v2(7230,4035)
OCTR: U3.6 U18.5 | length 2059.2
  Top Layer w10: U18.5 5517.2,3884.65 5535.44,3902.89 5595,3902.89 5602.07,3909.96 5602.07,3944.49 v2(5596.56,3950) ; U3.6 7322.24,4040.75 v2(7325,4037.99)
  Bottom Layer w10: v2(5596.56,3950) 5606.56,3940 5637.07,3940 5669.22,3972.15 5674.69,3972.15 5831.54,4129 7155.8,4129 7160.78,4124.02 7233.98,4124.02 7320,4037.99 v2(7325,4037.99)
ODRV5V: CN1.6 U22.15 | length 773.3
  Bottom Layer w10: U22.15 6397.48,3616.85 6418.24,3616.85 6441.76,3640.37 6579.44,3640.37 6593.44,3654.37 6953.96,3654.37 6991.48,3616.85 CN1.6
ODRV5V_2: U22.25
ODRV12IN: U22.5
ODRV33V: U22.6
ODRVGND: U22.16
ODRVGND_2: U22.26
ODRVSPI_CS: U22.30
ODRVSPI_MISO: U22.28
ODRVSPI_MOSI: U22.27
ODRVSPI_SCK: U22.29
POE+: C38.2 C59.1 C62.1 D30.1 D31.3 D32.3 R45.2 U17.1 U24.2 | length 2516.8
  Top Layer w15: D31.3 6297.62,3986.05 ; v1(6325,3970) 6308.95,3986.05 6297.62,3986.05 ; D32.3 6324.21,3916.73 C59.1 6297.62,3986.05 ; U17.1 6516.73,3686.73 6724.99,3894.99 C38.2 6761,3964.8 D30.1 ; v1(7295,3490) 7295.12,3490.12 C62.1 7460,3570.12 U24.2
  Bottom Layer w15: v1(6325,3970) 6445,3850 v1(6445,3685) 6470,3710 7140,3710 7195,3655 7195,3590 v1(7295,3490)
POE-: C59.2 D30.2 D31.4 D32.4 U17.4 U17.9 U21.1 | length 1035.4
  Top Layer w15: C59.2 6271.2,3864.41 U17.9 6314.31,3761.73 6344.31,3791.73 6344.31,3797.21 6359.14,3812.04 6364.62,3812.04 U17.4 6466.08,3913.5 D32.4 ; D31.4 6313.35,4112.89 D32.4 ; D30.2 6555.92,4050 D32.4 ; U21.1 6564.37,3861.87 D32.4
RJ1A: RJ1.4 U2.23 | length 847
  Top Layer w10: RJ1.4 5315.91,4500.91 5464.82,4649.82 5470,4644.64 5470,4630 5335,4495 5335,4485 5340,4480 5350,4480 v2(5410,4540) ; v2(5485,4470) 5587.6,4470 U2.23
  Bottom Layer w10: v2(5410,4540) 5415,4540 v2(5485,4470)
RJ1B: RJ1.5 U2.22 | length 856
  Top Layer w10: RJ1.5 5070,4456.12 5070,4375 5094.13,4350.87 5095.52,4350.87 5142.32,4304.08 5142.32,4302.68 5155,4290 5255,4290 5475,4510 U2.22
RJ2A: RJ1.1 U2.20 | length 546
  Top Layer w10: RJ1.1 5164.95,4370.44 5298.05,4370.44 5511.27,4583.66 5571.26,4583.66 U2.20
RJ2B: RJ1.2 U2.19 | length 539.9
  Top Layer w10: RJ1.2 5230.63,4415 5285,4415 5300,4430 5300,4454.59 ; 5302.46,4457.05 5307.7,4462.3 5315,4455 5315,4425 5320,4420 5325,4420 5565,4660 U2.19
RJ3A: RJ1.3 U2.17 | length 744.8
  Top Layer w10: v2(5520,4745) 5582.6,4745 U2.17
  Bottom Layer w10: RJ1.3@5154.95,4460.75 5154.95,4480.99 5112.47,4523.47 5112.47,4662.47 5195,4745 v2(5520,4745)
RJ3B: RJ1.6 U2.16 | length 734.9
  Top Layer w10: RJ1.6 5270,4626.2 5270,4714.14 5275.86,4720 5284.14,4720 5290,4714.14 5290,4600 5297.07,4592.93 5382.93,4592.93 5490,4700 5490,4775 5525,4810 U2.16
RJ4A: 
RJ4B: RJ1.8 U2.13 | length 669.3
  Top Layer w10: RJ1.8 5160,4726.57 5160,4800 5215,4855 5450,4855 5555,4960 U2.13
RS_485A: U22.23
RS_485B: U22.24
RST: C27.2 H1.5 R36.2 SW1.4 U3.29 U7.11 U12.37 U19.1 | length 8053.7
  Top Layer w10: 5348.26,3206.54 5348.26,3144.28 5370.74,3121.8 7494.64,3121.8 7541.4,3168.56 7541.4,3299.2 7621.2,3379 7753.8,3379 7787.93,3413.13 v2(7807.07,3413.13) ; 5348.28,3206.56 5348.28,3336.32 5372.09,3360.13 5382.49,3370.55 5409.34,3370.55 U7.11 ; U19.1 6084.66,3885 v2(6110.83,3911.16) ; U12.37 v2(6735,4937.32) ; C27.2 6929.65,4650.28 SW1.4 6978.04,4675.19 6978.04,4311.96 7050.75,4239.25 U3.29 7108.76,4232.99 7179.52,4232.99 7192.99,4219.52 7192.99,4148.76 7196.24,4152.01 v2(7240,4152.01)
  Bottom Layer w10: v2(6110.83,3911.16) 6113.7,3911.16 6138.01,3935.47 6138.01,3954.53 6129,3963.54 6129,4024 6206,4101 7091.46,4101 7205.47,3986.99 7419.16,3986.99 ; v2(6735,4937.32) 6882.68,4937.32 6942.67,4877.33 7126.85,4877.33 ; H1.5 7280,4980 7242.32,4942.32 7156.84,4942.32 7140.32,4925.8 7140.32,4890.8 7126.85,4877.33 ; v2(7807.07,3413.13) 7807.07,3780 7737.07,3850 7572.52,3850 7435.52,3986.99 7419.16,3986.99 ; 7126.85,4877.33 7230,4774.18 7230,4302.52 7147.01,4219.52 7147.01,4165.48 7160.48,4152.01 v2(7240,4152.01) 7254.14,4152.01 7419.16,3986.99
SCLK: H1.3 U3.17 U12.33 | length 1634.2
  Top Layer w10: U12.33 7248.29,4819.21 7273.92,4793.57 7314.6,4793.57 7454.68,4653.49 7454.68,4495 7449.02,4489.34 7449.02,4489.19 7386.82,4427 U3.17 7385,4427.24 v2(7385,4495)
  Bottom Layer w10: H1.3 7380,4952.86 7335.55,4908.41 7335.55,4544.45 v2(7385,4495)
SPDLED: R47.2 U12.24 | length 2938.1
  Top Layer w10: R47.2 5378.07,5055 v2(6305,5055) ; U12.24@6685,4602.68 6695,4592.68 v2(6695,4555)
  Bottom Layer w10: v2(6305,5055) 6547.54,5055 6833.01,4769.53 6833.01,4750.47 6819.53,4736.99 6806.84,4736.99 6761,4691.16 6761,4653.54 6751.99,4644.53 6751.99,4625.47 6765.47,4611.99 6784.53,4611.99 6798.01,4625.47 6798.01,4644.53 6789,4653.54 6789,4666.86 6861.01,4738.87 6861.01,4781.13 6864.4,4784.52 7063.95,4784.52 7069.52,4778.95 7069.52,4764.7 6859.82,4555 v2(6695,4555)
STEP: U22.12
THERMISTOR+: CN1.5 U22.13 | length 897.4
  Top Layer w10: U22.13 6309.57,3591.06 6323.71,3591.06 6339,3606.35 6339,3616.35 6377.02,3654.37 6953.96,3654.37 7070.22,3538.11 CN1.5
THERMISTOR-: U22.14
W5500CS: U3.14 U12.32 | length 1203
  Top Layer w10: U12.32 7248.15,4799.53 7268.12,4779.56 7308.81,4779.56 7431.69,4656.68 v2(7431.69,4508.92) ; v2(7385,4300) 7385,4290 7392.07,4282.93 7402.07,4282.93 7421.39,4302.24 U3.14
  Bottom Layer w10: v2(7385,4300) 7431.69,4346.69 v2(7431.69,4508.92)
W5500INT: U12.36
XTAL1: C46.2 U3.7 X1.1 | length 536.9
  Top Layer w10: U3.7 7365.39,4071.35 7365.39,4051.16 7378.14,4038.41 7677.51,4038.41 7693.97,4054.87 X1.1@7693.97,4214.48
XTAL2: C45.1 U3.8 X1.2 | length 895.9
  Top Layer w10: U3.8 7562.32,4083 7617.43,4138.11 7617.43,4142.43 7625,4150 7625,4504.01 7693.97,4572.98 7693.97,4739.57 C45.1@7688.54,4745
pads on no net: RJ1.7 SW1.2 SW1.3 U2.1 U2.4 U2.7 U2.10 U2.14 U7.2 U7.6 U7.7 U7.10 U7.14 U7.15 U7.16 U12.7 U12.12 U12.13 U12.18 U12.26 U12.27 U12.38 U12.39 U12.40 U12.41 U12.42 U12.46 U12.47 U17.7 U18.6 U19.3 U19.4 U19.5 U19.6 U19.11 U19.15 U25.5 U25.6 U25.7 USB1.A2 USB1.A3 USB1.A4 USB1.A8 USB1.A9 USB1.A10 USB1.A11 USB1.B2 USB1.B3 USB1.B4 USB1.B5 USB1.B6 USB1.B7 USB1.B8 USB1.B9 USB1.B10 USB1.B11
copper on no net: | length 674.7
  Top Layer w10: v2(5205,4720) 5175.98,4749.02 5175.98,4793.38 5221.62,4839.02 5456.62,4839.02 5527.61,4910 5597.6,4910
  Bottom Layer w10: 5154.95,4621.38 5154.95,4669.95 v2(5205,4720)

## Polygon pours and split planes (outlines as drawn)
AGND on Top Layer (solid, remove dead copper): 4775,3070 7880,3070 7880,5170 4775,5170
AGND on Bottom Layer (solid, remove dead copper, pour order 2): 4755,3000 7915,3000 7915,5195 4755,5195

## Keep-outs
Board Outline Layer:
  circle w10: c7715,4980 r62.5
  circle w10: c7715,3230 r62.5
  circle w10: c4965,4980 r62.5
  circle w10: c4965,3230 r62.5
  lines w10: 4840,3105 7840,3105 7840,5105 4840,5105 4840,3105

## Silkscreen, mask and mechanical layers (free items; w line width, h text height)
Top Silkscreen Layer:
  text "ICSP" at 7220,5035 h60
  text "0  1  2" at 6904.25,5019.22 h60
  text "LNK SPD" at 6900,4810 h60
  text "GND" at 7230,4775 h60
  text "RST" at 7039.41,4764.7 h40
  text "Octet Selection" at 5370,3925 h25
  text "1 2 4 8 16 32 64 128" at 5370,3890 h25
Bottom Silkscreen Layer:
  text "University Of Akron /  RMC Team /  2024" at 5518.27,4910 h40
  text "Lane Cline /  Eli Bukoski /  Garren Ward /  Jonathan Donley /  Alex Kinch /  Tatsuya Wachtl /  William Forcey /  Ethan Banning /  Seth McCord /  Logan Foster /  Zane Nold /  Liam Boich" at 6020,3875 h40
  text "O-Drive Rev Module" at 6985,3265 h120
  text "REV 1" at 6558.95,3137.8 h120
